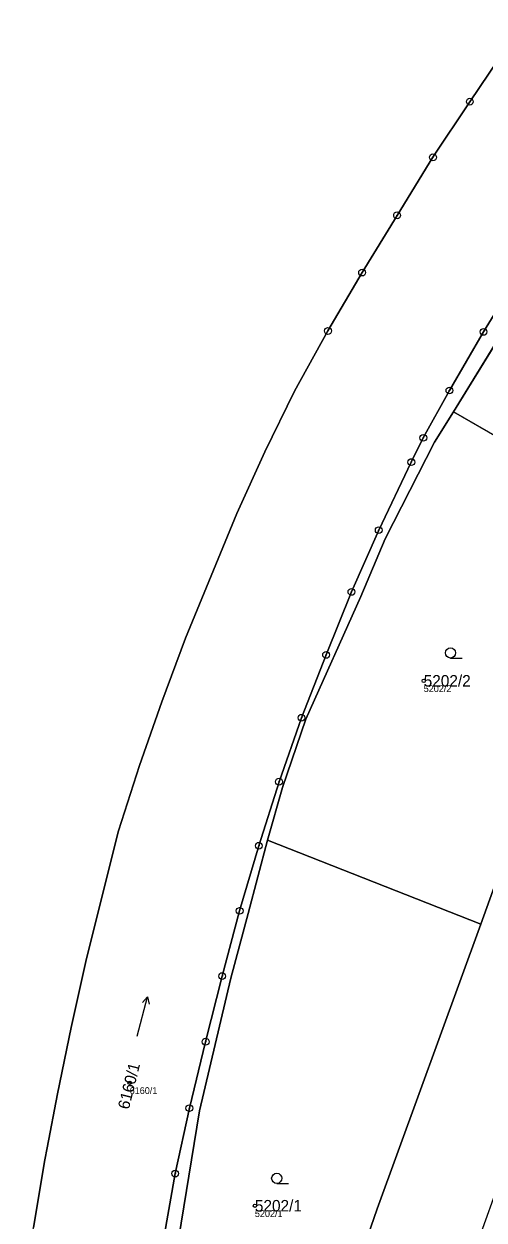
# Model space of a CAD drawing. Extents: x -690132 to -685994, y -975441 to -972444.
# Drawn here: x -689059.6 to -688991.5, y -973507.9 to -973331.2 of the extents above; entities that cross this region are included whole.
import ezdxf

# ---------------------------------------------------------------- set-up
doc = ezdxf.new("R2010")
doc.units = 0
for name, color, linetype in [('Definiční body', 7, 'Continuous'), ('Hranice parcel', 7, 'Continuous'), ('Parcelní čísla', 7, 'Continuous'), ('Polygon ku', 7, 'Continuous'), ('Polygon parcely', 7, 'Continuous'), ('Značky bodu BP', 7, 'Continuous'), ('Značky kultur', 7, 'Continuous')]:
    doc.layers.add(name, color=color, linetype=linetype)

msp = doc.modelspace()

# ---------------------------------------------------------------- linework, layer by layer
at = {"layer": 'Definiční body'}
for centre in [(-689000.45, -973428.24), (-689043.92, -973487.61), (-689025.41, -973505.78)]:
    msp.add_circle(centre, 0.25, dxfattribs=at)
at = {"layer": 'Hranice parcel'}
for p, q in [((-688999.08, -973350.91), (-688993.63, -973342.69)), ((-689004.39, -973359.48), (-688999.08, -973350.91)), ((-688982.01, -973365.67), (-688996.04, -973388.53)), ((-689019.53, -973385.43), (-689014.6, -973376.56)), ((-689023.96, -973394.43), (-689019.53, -973385.43)), ((-688967.84, -973404.77), (-688996.04, -973388.53)), ((-689039.16, -973431.33), (-689035.65, -973421.95)), ((-689042.48, -973440.74), (-689039.16, -973431.33)), ((-689045.55, -973450.38), (-689042.48, -973440.74)), ((-689047.97, -973460.01), (-689045.55, -973450.38)), ((-688991.99, -973464.18), (-689023.53, -973451.79)), ((-689050.42, -973469.71), (-689047.97, -973460.01)), ((-689052.55, -973479.46), (-689050.42, -973469.71)), ((-689054.57, -973489.26), (-689052.55, -973479.46)), ((-689056.13, -973497.22), (-689054.57, -973489.26)), ((-689056.48, -973499.01), (-689056.13, -973497.22))]:
    msp.add_line(p, q, dxfattribs=at)
for points in [[(-688993.63, -973342.69), (-688988.02, -973334.37), (-688982.03, -973326.27)], [(-689014.6, -973376.56), (-689009.56, -973367.94), (-689004.39, -973359.48)], [(-688984.12, -973364.71), (-688986.33, -973368.13), (-688991.61, -973376.7), (-688996.65, -973385.35), (-689000.51, -973392.34), (-689002.28, -973395.93), (-689007.1, -973405.99), (-689011.14, -973415.11), (-689014.88, -973424.41), (-689018.51, -973433.7), (-689021.84, -973443.14), (-689024.82, -973452.6), (-689027.66, -973462.22), (-689030.24, -973471.86), (-689032.69, -973481.55), (-689035.1, -973491.37), (-689037.19, -973501.03), (-689038.92, -973510.83)], [(-688996.04, -973388.53), (-688998.83, -973392.98), (-689006.13, -973407.29), (-689009.76, -973415.78), (-689017.88, -973433.9), (-689021.32, -973444.02), (-689023.53, -973451.79)], [(-689035.65, -973421.95), (-689031.85, -973412.72), (-689028.06, -973403.5), (-689023.96, -973394.43)], [(-688991.99, -973464.18), (-688979.76, -973430.24), (-688973.73, -973415.09), (-688968.74, -973406.23), (-688967.84, -973404.77)], [(-689023.53, -973451.79), (-689026.39, -973462.62), (-689028.98, -973472.17), (-689033.6, -973491.75), (-689037.12, -973513.19), (-689040.5, -973540.56), (-689041.58, -973557.37), (-689041.89, -973569.04)], [(-689016.73, -973564.31), (-689017.27, -973562.27), (-689018.15, -973554.17), (-689017.85, -973542.83), (-689017.44, -973534), (-689014.27, -973526.32), (-689007.32, -973506.23), (-688991.99, -973464.18)], [(-689059.56, -973518.91), (-689058.15, -973508.97), (-689056.48, -973499.01)]]:
    msp.add_lwpolyline(points, dxfattribs=at)
at = {"layer": 'Polygon ku'}
for points in [[(-688982.03, -973326.27), (-688988.02, -973334.37), (-688993.63, -973342.69), (-688999.08, -973350.91), (-689004.39, -973359.48), (-689009.56, -973367.94), (-689014.6, -973376.56), (-689019.53, -973385.43), (-689023.96, -973394.43), (-689028.06, -973403.5), (-689031.85, -973412.72), (-689035.65, -973421.95)], [(-689035.65, -973421.95), (-689039.16, -973431.33), (-689042.48, -973440.74), (-689045.55, -973450.38), (-689047.97, -973460.01), (-689050.42, -973469.71), (-689052.55, -973479.46), (-689054.57, -973489.26), (-689056.13, -973497.22), (-689056.48, -973499.01), (-689058.15, -973508.97)]]:
    msp.add_lwpolyline(points, dxfattribs=at)
at = {"layer": 'Polygon parcely'}
for points in [[(-688982.03, -973326.27), (-688988.02, -973334.37), (-688993.63, -973342.69), (-688999.08, -973350.91), (-689004.39, -973359.48), (-689009.56, -973367.94), (-689014.6, -973376.56), (-689019.53, -973385.43), (-689023.96, -973394.43), (-689028.06, -973403.5), (-689031.85, -973412.72), (-689035.65, -973421.95), (-689039.16, -973431.33), (-689042.48, -973440.74), (-689045.55, -973450.38), (-689047.97, -973460.01), (-689050.42, -973469.71)], [(-689037.12, -973513.19), (-689033.6, -973491.75), (-689028.98, -973472.17), (-689026.39, -973462.62), (-689023.53, -973451.79), (-689021.32, -973444.02), (-689017.88, -973433.9), (-689009.76, -973415.78), (-689006.13, -973407.29), (-688998.83, -973392.98), (-688996.04, -973388.53), (-688982.01, -973365.67)], [(-688986.33, -973368.13), (-688991.61, -973376.7), (-688996.65, -973385.35), (-689000.51, -973392.34), (-689002.28, -973395.93), (-689007.1, -973405.99), (-689011.14, -973415.11), (-689014.88, -973424.41), (-689018.51, -973433.7), (-689021.84, -973443.14), (-689024.82, -973452.6), (-689027.66, -973462.22), (-689030.24, -973471.86), (-689032.69, -973481.55), (-689035.1, -973491.37), (-689037.19, -973501.03), (-689038.92, -973510.83)], [(-689038.92, -973510.83), (-689037.19, -973501.03), (-689035.1, -973491.37), (-689032.69, -973481.55), (-689030.24, -973471.86), (-689027.66, -973462.22), (-689024.82, -973452.6), (-689021.84, -973443.14), (-689018.51, -973433.7), (-689014.88, -973424.41), (-689011.14, -973415.11), (-689007.1, -973405.99), (-689002.28, -973395.93), (-689000.51, -973392.34), (-688996.65, -973385.35), (-688991.61, -973376.7), (-688986.33, -973368.13)], [(-688994.68, -973517.34), (-688987.85, -973498.39), (-688979.84, -973476.15), (-688972.03, -973454.25), (-688963.19, -973429.49), (-688955.06, -973414.81), (-688951.86, -973409.8), (-688944.91, -973400.79), (-688939.84, -973395.32), (-688935.64, -973392.84), (-688933.74, -973392.19), (-688936.99, -973389.94), (-688939.8, -973388.03), (-688946.51, -973387.83), (-688946.9, -973387.59), (-688954.18, -973383.09), (-688954.84, -973384.14), (-688967.84, -973404.77), (-688968.74, -973406.23), (-688973.73, -973415.09), (-688979.76, -973430.24), (-688991.99, -973464.18), (-689007.32, -973506.23), (-689014.27, -973526.32)], [(-689050.42, -973469.71), (-689052.55, -973479.46), (-689054.57, -973489.26), (-689056.13, -973497.22), (-689056.48, -973499.01), (-689058.15, -973508.97)]]:
    msp.add_lwpolyline(points, dxfattribs=at)
for points in [[(-688982.01, -973365.67), (-688996.04, -973388.53), (-688967.84, -973404.77), (-688954.84, -973384.14), (-688954.18, -973383.09), (-688973.05, -973371.01), (-688980.91, -973366.55)], [(-688973.73, -973415.09), (-688968.74, -973406.23), (-688967.84, -973404.77), (-688996.04, -973388.53), (-688998.83, -973392.98), (-689006.13, -973407.29), (-689009.76, -973415.78), (-689017.88, -973433.9), (-689021.32, -973444.02), (-689023.53, -973451.79), (-688991.99, -973464.18), (-688979.76, -973430.24)], [(-689017.85, -973542.83), (-689017.44, -973534), (-689014.27, -973526.32), (-689007.32, -973506.23), (-688991.99, -973464.18), (-689023.53, -973451.79), (-689026.39, -973462.62), (-689028.98, -973472.17), (-689033.6, -973491.75), (-689037.12, -973513.19), (-689040.5, -973540.56), (-689041.58, -973557.37), (-689041.89, -973569.04), (-689041.29, -973568.94), (-689016.73, -973564.31), (-689017.27, -973562.27), (-689018.15, -973554.17)]]:
    msp.add_lwpolyline(points, close=True, dxfattribs=at)
at = {"layer": 'Značky bodu BP'}
for centre, radius in [((-688993.63, -973342.69), 0.5), ((-688993.63, -973342.69), 0.0303), ((-688999.08, -973350.91), 0.5), ((-688999.08, -973350.91), 0.0303), ((-689004.39, -973359.48), 0.5), ((-689004.39, -973359.48), 0.0303), ((-689009.56, -973367.94), 0.5), ((-689009.56, -973367.94), 0.0303), ((-689014.6, -973376.56), 0.5), ((-689014.6, -973376.56), 0.0303), ((-688991.61, -973376.7), 0.5), ((-688991.61, -973376.7), 0.0303), ((-688996.65, -973385.35), 0.5), ((-688996.65, -973385.35), 0.0303), ((-689000.51, -973392.34), 0.5), ((-689000.51, -973392.34), 0.0303), ((-689002.28, -973395.93), 0.5), ((-689002.28, -973395.93), 0.0303), ((-689007.1, -973405.99), 0.5), ((-689007.1, -973405.99), 0.0303), ((-689011.14, -973415.11), 0.5), ((-689011.14, -973415.11), 0.0303), ((-689014.88, -973424.41), 0.5), ((-689014.88, -973424.41), 0.0303), ((-689018.51, -973433.7), 0.5), ((-689018.51, -973433.7), 0.0303), ((-689021.84, -973443.14), 0.5), ((-689021.84, -973443.14), 0.0303), ((-689024.82, -973452.6), 0.5), ((-689024.82, -973452.6), 0.0303), ((-689027.66, -973462.22), 0.5), ((-689027.66, -973462.22), 0.0303), ((-689030.24, -973471.86), 0.5), ((-689030.24, -973471.86), 0.0303), ((-689032.69, -973481.55), 0.5), ((-689032.69, -973481.55), 0.0303), ((-689035.1, -973491.37), 0.5), ((-689035.1, -973491.37), 0.0303), ((-689037.19, -973501.03), 0.5), ((-689037.19, -973501.03), 0.0303)]:
    msp.add_circle(centre, radius, dxfattribs=at)
at = {"layer": 'Značky kultur'}
for p, q in [((-688996.5, -973424.87), (-688994.75, -973424.87)), ((-689042.82, -973480.73), (-689041.27, -973474.94)), ((-689041.27, -973474.94), (-689042.01, -973475.75)), ((-689041.27, -973474.94), (-689041.04, -973476.01)), ((-689022.18, -973502.48), (-689020.43, -973502.48))]:
    msp.add_line(p, q, dxfattribs=at)
for centre in [(-688996.5, -973424.12), (-689022.18, -973501.73)]:
    msp.add_circle(centre, 0.75, dxfattribs=at)

# ---------------------------------------------------------------- texts
at = {"layer": 'Definiční body'}
for s, p in [('5202/2', (-689000.45, -973429.9)), ('6160/1', (-689043.92, -973489.27)), ('5202/1', (-689025.41, -973507.44))]:
    msp.add_text(s, height=1, dxfattribs=at).set_placement(p)
at = {"layer": 'Parcelní čísla'}
for s, p in [('5202/2', (-689000.45, -973429.09)), ('5202/1', (-689025.41, -973506.63))]:
    msp.add_text(s, height=1.7, dxfattribs=at).set_placement(p)
msp.add_text('6160/1', height=1.7, rotation=76, dxfattribs=at).set_placement((-689044.05, -973491.65))

doc.saveas('drawing.dxf')
